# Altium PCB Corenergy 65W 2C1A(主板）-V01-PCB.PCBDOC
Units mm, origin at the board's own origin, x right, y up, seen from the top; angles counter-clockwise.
Board outline 87.3 x 91.75 mm, 2 copper layers (Top Layer, Bottom Layer), stack 0.325 mm thick; 53 components, 103 nets, 136 pads, 181 vias.
Unrouted connection lines stored in the file: 2.
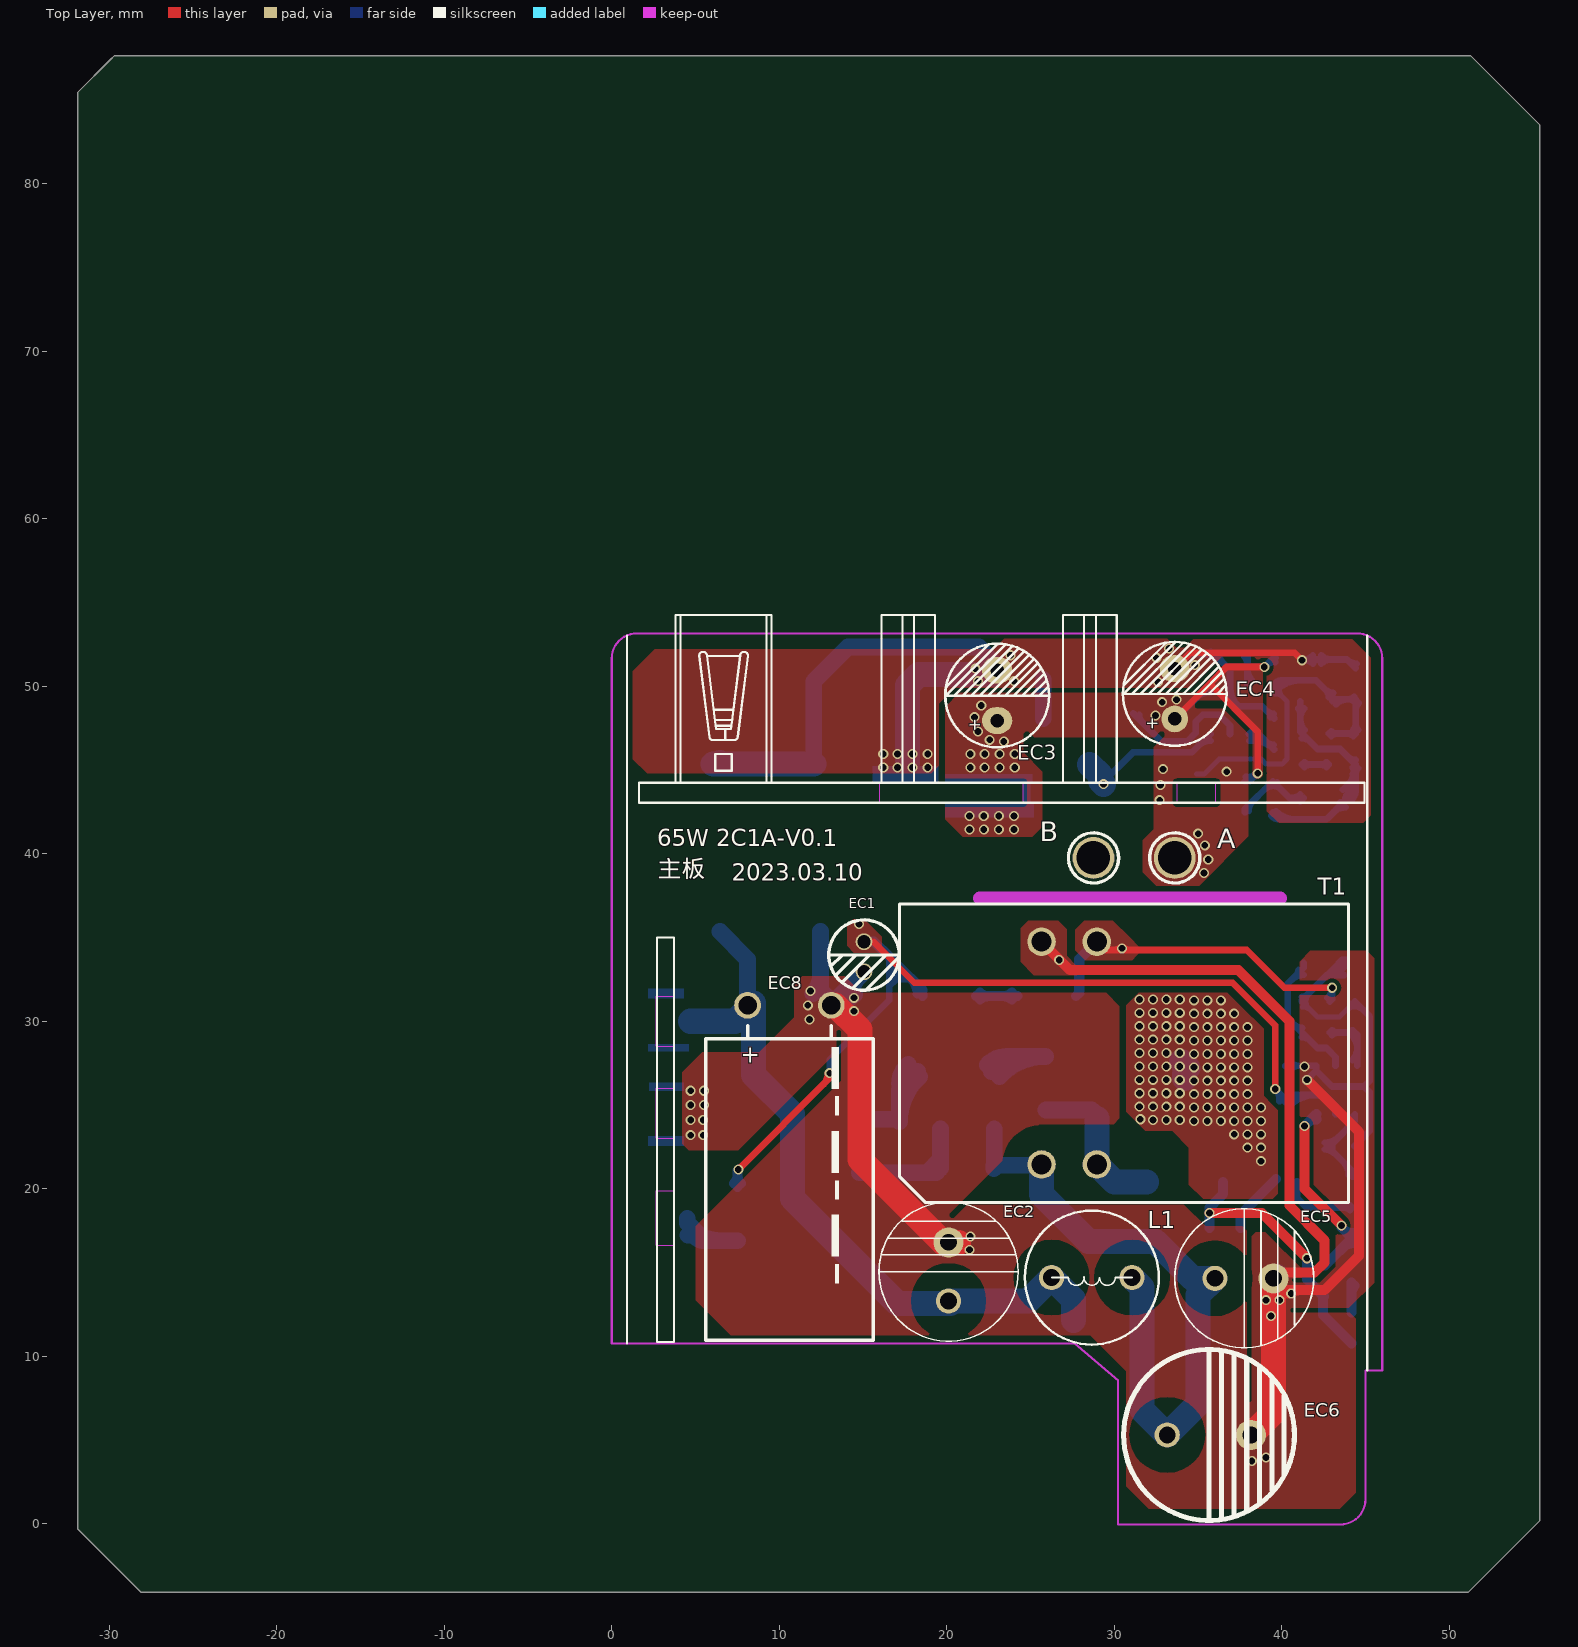
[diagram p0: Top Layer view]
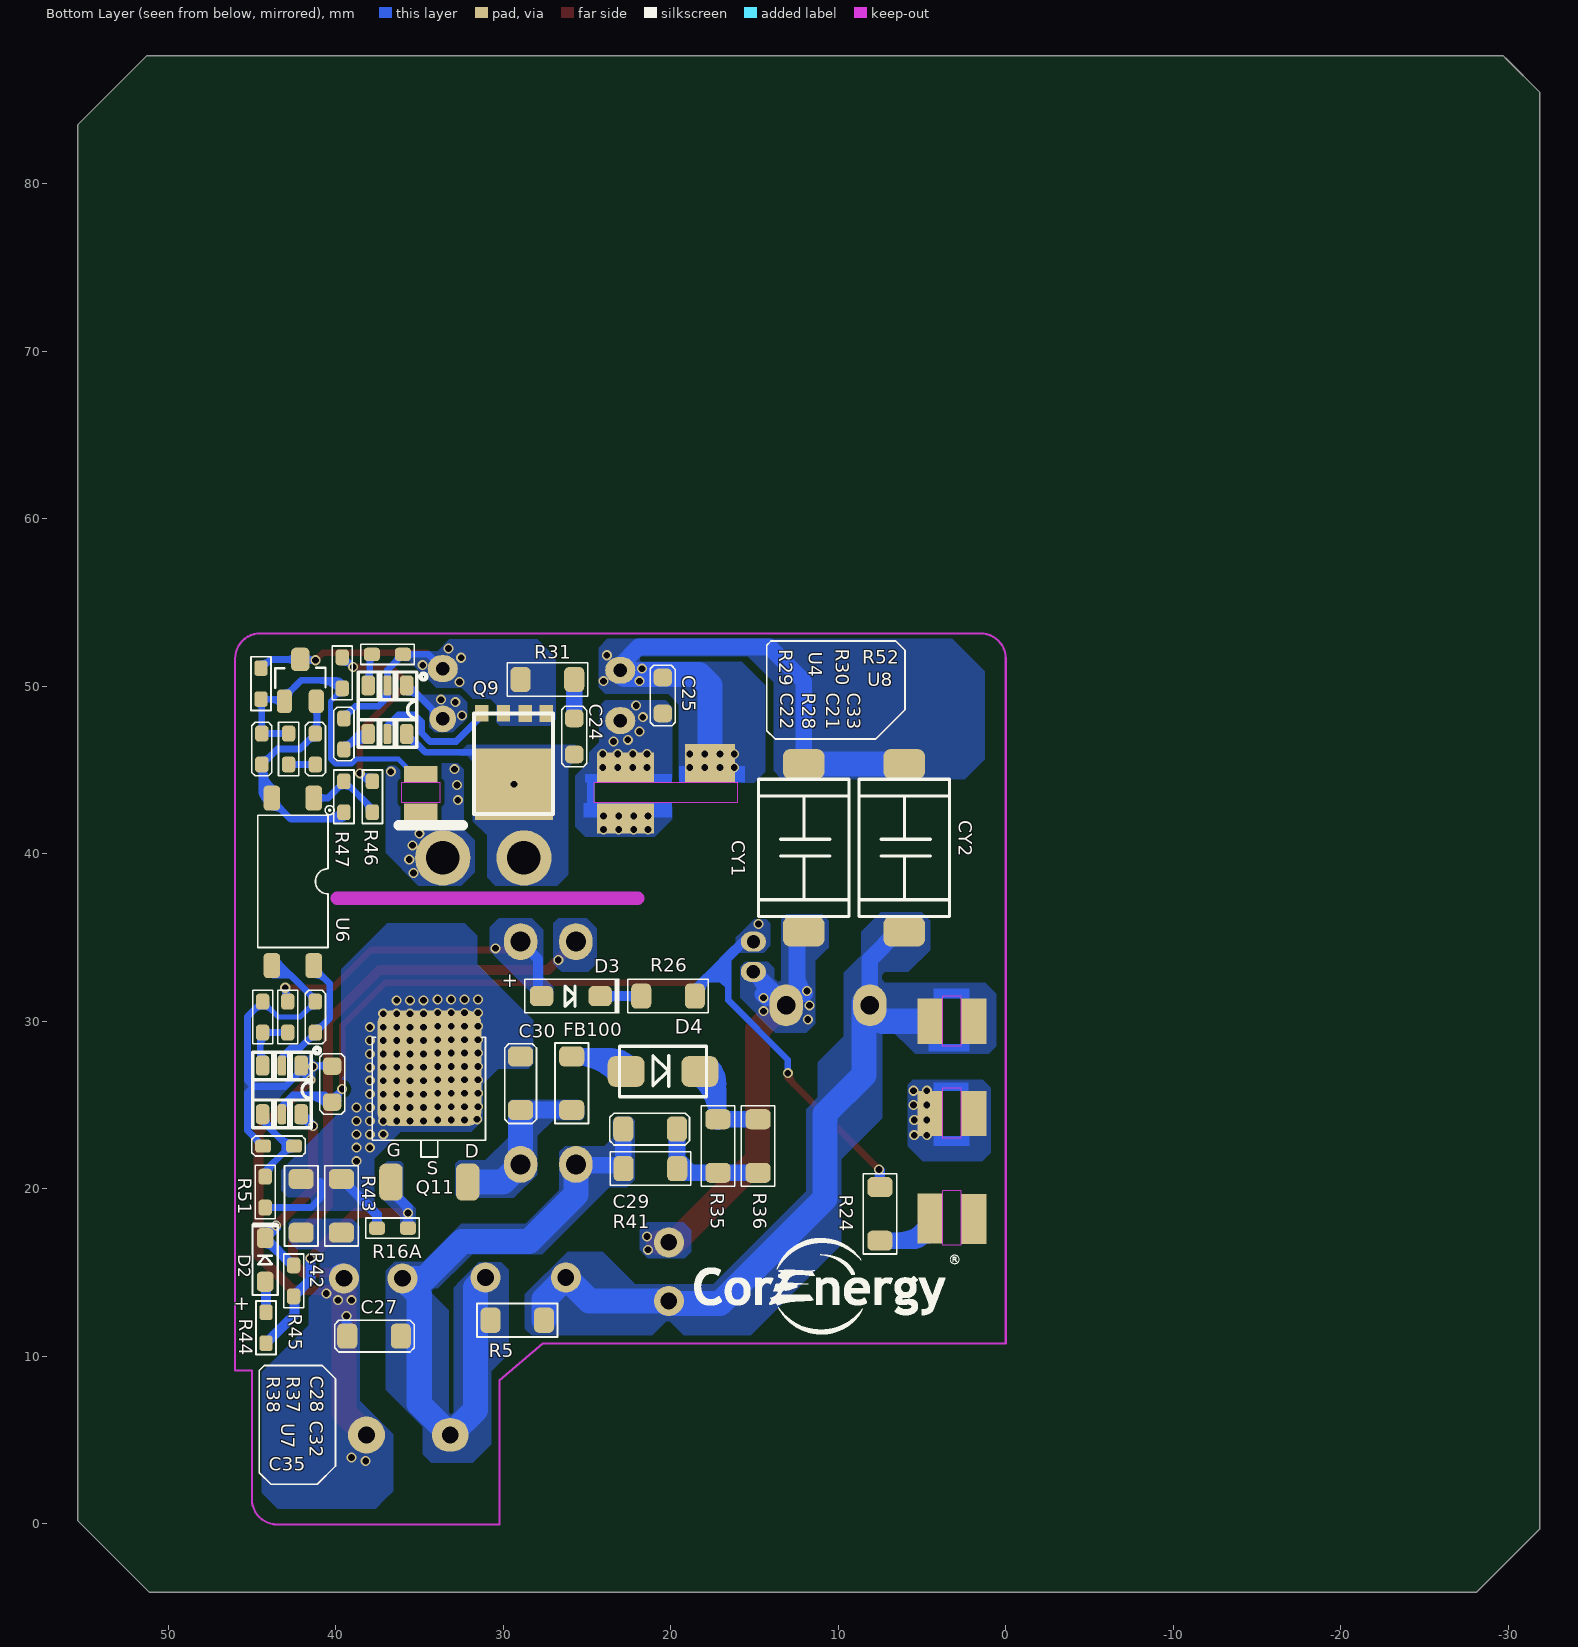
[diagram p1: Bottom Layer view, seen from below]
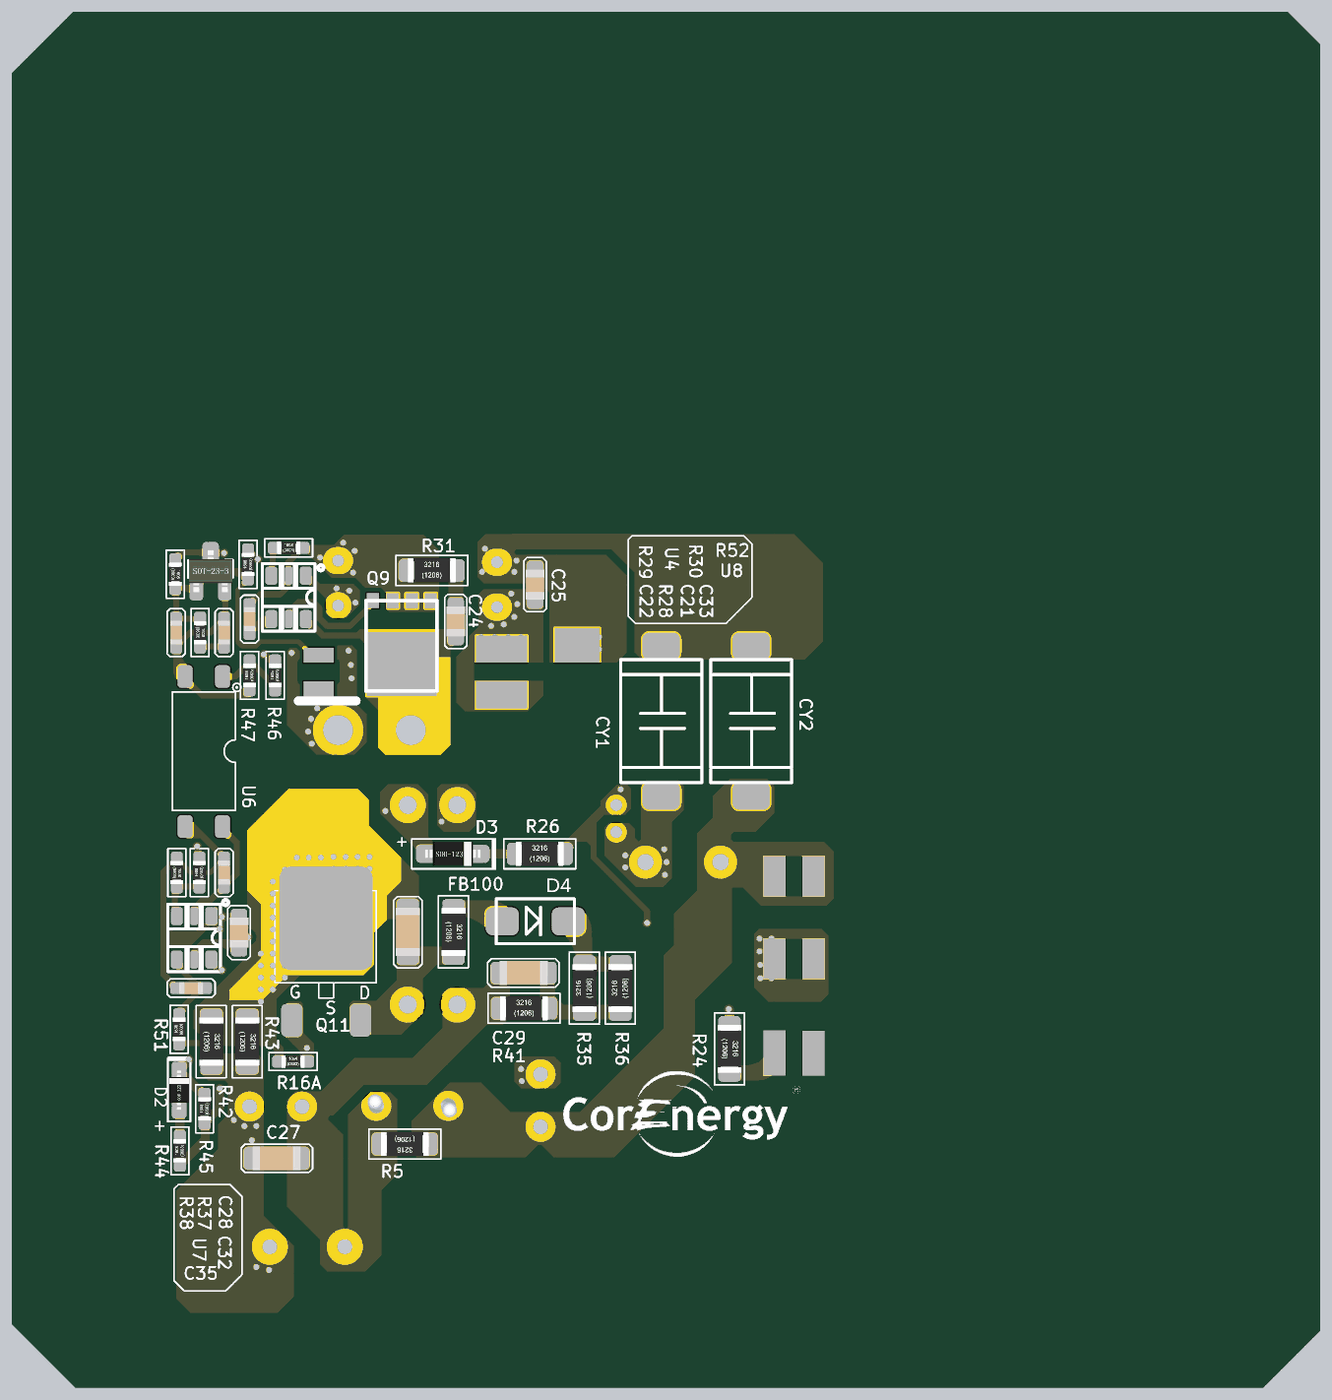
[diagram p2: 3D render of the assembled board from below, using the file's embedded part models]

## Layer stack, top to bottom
Top Layer: signal copper 0.0356
Dielectric: core 0.254, FR-4, Dk 4.2
Bottom Layer: signal copper 0.0356

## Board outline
-29.7,87.65 51.25,87.65 55.4,83.5 55.4,0.2 51.1,-4.1 -28.1,-4.1 -31.9,-0.3 -31.9,85.45 -29.95,87.4

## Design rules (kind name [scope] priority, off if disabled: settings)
Clearance Clearance_1 [InNet('GND') vs InNetClass('New Class')] p1: gap=1.5
Clearance [All] p2: gap=0.25
ComponentClearance [All] p1: gap=0 collisioncheckmode=3 verticalgap=0 showdistances=FALSE
FabricationTestpoint [(IsPad And (OnTopLayer Or OnBottomLayer))] p1: side=3 testpointundercomponent=TRUE minsize=1.016 maxsize=2.54 preferedsize=1.524 minholesize=0 maxholesize=1.016 preferedholesize=0.813 testpointgrid=0.025 allowsidetop=TRUE allowsidebottom=TRUE usegrid=TRUE gridtolerance=0
PolygonConnect [All] p1: connectstyle=Direct reliefconductorwidth=0.254 reliefentries=4 polygonreliefangle="90 Angle" airgapwidth=0.254
RoutingVias [All] p1: holewidth=0.3 width=0.5 viastyle="Through Hole" minholewidth=0.3 minwidth=0.5 maxholewidth=10 maxwidth=10
SilkToSolderMaskClearance SilkscreenOverComponentPads [IsPad] p1: minsilkscreentomaskgap=0.254 clearancetoexposedcopper=TRUE
SolderMaskExpansion [All] p1: expansion=0.102
Width [All] p1: maxlimit=10 minlimit=0.2 preferedwidth=0.4
25 further rules are at their usual default settings.

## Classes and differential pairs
net class "New Class": NetC27_1 NetC30_1 VH

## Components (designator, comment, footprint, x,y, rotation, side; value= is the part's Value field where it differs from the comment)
C21 "100nF" 0603C 41.2,46.25 r270 bottom (schematic designator C6)
C22 "100pF" 0603C 44.4,46.25 r90 bottom
C24 "1nF/250V" 0805C 25.75,47 r270 bottom (schematic designator C2)
C25 "100nF/50V" 0805C 20.46,49.447 r270 bottom
C27 "1nF/1KV" 1206C 37.7,11.2 r0 bottom (schematic designator C13)
C28 "1nF/50V" 0603C 41.2,30.25 r90 bottom (schematic designator C9)
C29 "1nF/1KV" 1206C 21.221,23.563 r180 bottom (schematic designator C1)
C30 "NC" 1206C 28.95,26.3 r90 bottom (schematic designator R20)
C32 "100NF/100V" 0805C 40.2,26.25 r90 bottom (schematic designator C8)
C33 "2.2uF/25V" 0603C 39.5,47.15 r90 bottom (schematic designator C4)
C35 "100PF" 0603C 43.4,22.55 r180 bottom (schematic designator C10)
CY1 "" SMD-YC 12.05,40.35 r270 bottom
CY2 "" SMD-YC 6.05,40.35 r270 bottom (schematic designator CY1)
D2 "IN4148" 323 44.2,15.75 r270 bottom
D3 "ES1JS" 123 25.95,31.5 r0 bottom (schematic designator D4)
D4 "S2MF" SMAF 20.45,27 r180 bottom (schematic designator D1)
EC1 "4.7uF/100V" RB4.0 15.05,34.95 r270 top (schematic designator EC8)
EC2 "25uF/400V" 8*12 20.1,15.05 r180 top
EC3 "470uF/25V" C-DIP-6.2/3.0#1 23,49.45 r0 top locked (schematic designator EC7)
EC4 "470uF/25V" C-DIP-6.2/3.0#2 33.6,49.55 r0 top locked (schematic designator EC6)
EC5 "25uF/400V" 8*12 37.75,14.65 r90 top
EC6 "33uF/400V" E10 35.65,5.3 r0 top (schematic designator CE5)
EC8 "33uF/400V" EC-CAP10HA16 8.1,30.95 r90 top locked
FB100 "0R" 1206R 25.9,26.3 r270 bottom
L1 "HWR8*12/40uH" T8*10 28.65,14.7 r180 top
Q9 "HGN070N12SL" Q-QFN5*6 32.2,41.85 r90 bottom (schematic designator Q1)
Q11 "CE65H270TOEI" Cascode-TO252-3L 34.4,23.8 r180 bottom
R5 "4.7K" 1206R 29.15,12.15 r0 bottom (schematic designator R1)
R16A "10K" 0603R 36.6,17.65 r180 bottom (schematic designator R20)
R24 "200k" 1206R 7.5,18.5 r270 bottom (schematic designator R12)
R26 "2R" 1206R 20.15,31.5 r180 bottom (schematic designator R9)
R28 "10k" 0603R 42.8,46.25 r270 bottom (schematic designator R16)
R29 "3.6K" 0603R 44.45,50.15 r270 bottom (schematic designator R14)
R30 "27.4K" 0603R 39.6,50.8 r90 bottom (schematic designator R19)
R31 "5.1R" 1206R 27.35,50.4 r180 bottom (schematic designator R1)
R35 "22R" 1206R 17.173,22.55 r90 bottom (schematic designator R5)
R36 "22R" 1206R 14.773,22.55 r90 bottom (schematic designator R5)
R37 "150k" 0603R 42.85,30.25 r90 bottom (schematic designator R16)
R38 "13k" 0603R 44.35,30.25 r270 bottom (schematic designator R24)
R41 "470K" 1206R 21.2,21.2 r180 bottom (schematic designator R2)
R42 "0.56R" 1206R 42.05,18.978 r270 bottom (schematic designator R23)
R43 "0.56R" 1206R 39.65,18.978 r270 bottom (schematic designator R22)
R44 "10R" 0603R 44.15,11.7 r90 bottom (schematic designator R15)
R45 "20R" 0603R 42.5,14.5 r90 bottom (schematic designator R17)
R46 "5.6K" 0603R 37.8,43.4 r90 bottom (schematic designator R11)
R47 "4.7K" 0603R 39.5,43.4 r90 bottom (schematic designator R13)
R51 "100R" 0603R 44.2,19.8 r90 bottom (schematic designator R21)
R52 "20K" 0603R 36.9,51.9 r180 bottom (schematic designator R8)
T1 "Comment" ATQ2516 30.6,28.1 r0 top locked
U4 "TL431" SOT-23 42.1,50.35 r180 bottom
U6 "EL1019" W_SO-4(P10)__EL1019 42.55,38.3 r270 bottom (schematic designator U3)
U7 "HY1602E" SOT-23-6 43.2,25.9 r270 bottom (schematic designator U2)
U8 "HY913" SOT-23-6 36.9,48.6 r270 bottom

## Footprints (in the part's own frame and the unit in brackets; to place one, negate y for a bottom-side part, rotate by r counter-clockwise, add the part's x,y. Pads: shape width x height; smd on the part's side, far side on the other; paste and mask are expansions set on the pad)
8*12 [mm]
  round 1.5 / inner round 1.8 / far side round 1.8 hole 1: 1(0,1.75)
  round 1.8 hole 1: 2(0,-1.75)
  silkscreen extent -4.15,-4.15 4.15,4.15
123 [mm]
  rrect50% 1.4x1.2 smd mask+0.03: 1(1.75,0) 2(-1.75,0)
  silkscreen extent -2.9,-1.05 2.75,1.05, body extent -1.85,-0.8 1.85,0.8, height 1.2
323 [mm]
  rrect50% 1.2x1 smd mask+0.03: 1(1.3,0) 2(-1.3,0)
  silkscreen extent -2.25,-0.75 2.1,0.75, body extent -1.3,-0.65 1.3,0.65, height 1
0603C [mm]
  rrect50% 0.95x0.8 smd mask+0.03: 1(-0.925,0) 2(0.925,0)
  silkscreen extent -1.6,-0.6 1.6,0.6, body extent -0.8,-0.4 0.8,0.4, height 0.8
0603R [mm]
  rrect50% 0.95x0.8 smd mask+0.03: 1(-0.925,0) 2(0.925,0)
  silkscreen extent -1.6,-0.6 1.6,0.6, body extent -0.77,-0.42 0.78,0.43, height 0.45
0805C [mm]
  rrect50% 1.05x1.1 smd mask+0.03: 1(-1.075,0) 2(1.075,0)
  silkscreen extent -1.8,-0.75 1.8,0.75, body extent -1,-0.62 1,0.63, height 0.6
1206C [mm]
  rrect50% 1.2x1.5 smd mask+0.03: 1(-1.6,0) 2(1.6,0)
  silkscreen extent -2.4,-0.95 2.35,0.95, body extent -1.6,-0.8 1.6,0.8, height 0.79
1206R [mm]
  rrect50% 1.2x1.5 smd mask+0.03: 1(-1.6,0) 2(1.6,0)
  silkscreen extent -2.4,-1 2.4,1, body extent -1.6,-0.8 1.6,0.8, height 0.55
ATQ2516 [mm]
  round 1.7 / inner round 1.7 / far side oval 2x2.2 hole 1.2: 1(-4.95,-6.65) 2(-1.65,-6.65) 7(-1.65,6.65) 8(-4.95,6.65)
  silkscreen extent -13.42,-8.93 13.39,8.9, body extent -13.43,-8.95 13.45,8.97, height 20.5
C-DIP-6.2/3.0#1 [mm]
  oval 1.8x1.6 hole 0.8: 1(0,-1.5) 2(0,1.5)
  silkscreen extent -3.1,-3.1 3.1,3.1
C-DIP-6.2/3.0#2 [mm]
  round 1.6 hole 0.8: 1(0,-1.5)
  oval 1.8x1.6 hole 0.8: 2(0,1.5)
  silkscreen extent -3.1,-3.1 3.1,3.1
Cascode-TO252-3L [mm]
  rrect50% 1.4x2.2 smd mask+0.03: 1(-2.29,-3.4) 3(2.29,-3.4)
  rrect25% 6.2x6.9 smd mask+0.03: 2(0,3.4)
  silkscreen extent -3.4,-1.9 3.35,5.25, body extent -3.3,-3.8 3.3,6.25, height 1.1
E10 [mm]
  round 1.5 / inner round 1.45 / far side oval 2.2x2 hole 1: 1(-2.5,0)
  round 1.8 / inner round 1.45 / far side round 2.2 hole 1: 2(2.5,0)
  silkscreen extent -5.1,-5.1 5.1,5.1
EC-CAP10HA16 [mm]
  round 1.6 / inner oval 2.5x2 / far side oval 2.5x2 hole 1.1: 1(0,0) 2(0,-5)
  silkscreen extent -20,-7.5 -1.2,2.5
Q-QFN5*6 [mm]
  rect 4.25x4.65 smd: D(2.3,-2.85)
  rect 1x0.8 smd: G(6.54,-0.92) S(6.52,-4.78) S(6.52,-3.52) S(6.53,-2.23)
  silkscreen extent 0.52,-5.19 6.52,-0.46
RB4.0 [mm]
  round 1 / inner oval 1.2x1.5 / far side oval 1.2x1.5 hole 0.8: 1(0.2,0) 2(2,0.001)
  silkscreen extent -1.1,-2.1 3.1,2.1
SMAF [mm]
  rrect50% 2.2x1.85 smd: 1(-2.2,0) 2(2.2,0)
  silkscreen extent -2.6,-1.5 2.6,1.5
SMD-YC [mm]
  rrect50% 1.8x2.5 smd: 1(5,0) 2(-5,0)
  silkscreen extent -4.1,-2.7 4.1,2.7
SOT-23 [mm]
  rrect50% 0.9x1.4 smd mask+0.03: 1(-0.95,-1.25) 3(0.95,-1.25)
  rrect50% 1.1x1.4 smd mask+0.03: 2(0,1.25)
  silkscreen extent -1.5,-0.45 1.5,0.75, body extent -1.45,-1.4 1.45,1.4, height 1.2
SOT-23-6 [mm]
  rrect50% 1.2x0.8 smd mask+0.03: 1(-1.45,1.15) 3(-1.45,-1.15) 4(1.45,-1.15) 6(1.45,1.15)
  rrect50% 1.2x0.5 smd mask+0.03: 2(-1.45,0) 5(1.45,0)
  silkscreen extent -2.53,-1.75 2.25,2.28
T8*10 [mm] "磁环电感"
  round 1.5 / inner round 1.5 / far side round 1.8 hole 1: 1(-2.4,0) 2(2.4,0)
  silkscreen extent -4,-4 4,4, body extent -3.5,-3.5 3.5,3.5, height 10.92
W_SO-4(P10)__EL1019 [mm]
  rrect50% 1.5x1 smd: 1(-5.025,1.25) 2(-5.025,-1.25) 3(4.975,-1.251) 4(4.975,1.25)
  silkscreen extent -4.57,-2.1 3.9,2.47

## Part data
C21 C22: library part CAP-1, "1206-big"
C24 C25 C30 C32: library part C0805, "cap"
C27 C29: library part CAP, "1NF/630V，COG/NPO,±5%,1206,C1206N102J631T"
C28: library part C0402, "cap"
C33 C35: library part C0603, "cap"
CY1 CY2: library part CY, "CY"
D2 D3 D4: library part DIODE, "Diode"
EC1 EC8: library part CE10
EC2 EC5 EC6: library part CE10, "27uF/400V，10*15mm"
EC3 EC4: library part CT6, "CAP-E"
FB100 R5 R16A R24 R26 R31 R35 R36 R38 R41 R42 R43 R45 R51 R52: library part RES, "resistance"
L1: library part IND-C, "ferrite inductor"
Q9: library part DFN8*8, "A1SH MOS管 AO3401"
Q11: library part DFN8*8
R28 R29 R30 R46 R47: library part RSE2
R37: library part RES2
R44: library part RES, "2R,±1%,0402"
U6: library part PC817, "EL1018（TA)(AES)-VG,SOP-4_P2.54_300mil,EVERLIGHT(台湾亿光)"
U7: library part MK2697G
U8: library part SC3503

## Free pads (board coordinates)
  rect 1.5x3 smd far side mask+0.03: 0(1.9,18.2) 0(4.5,18.222)
  rect 1.5x2.7 smd far side mask+0.03: 0(1.9,24.5) 0(1.9,30) 0(4.5,24.5) 0(4.5,30)
  rect 3x2.3 smd far side: 0(17.65,45.4)
  rect 3.4x1.8 smd far side: 0(22.7,42.1) 0(22.7,45.15)
  round 2.5 / inner round 2.5 / far side round 3.3 hole 2 mask+0.03: 0(28.75,39.75) 0(33.6,39.75)
  rect 2x1 smd far side: 0(34.9,42.5) 0(34.9,44.75)

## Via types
v1: diameter 0.6, hole 0.4, Top Layer to Bottom Layer, tented both sides, 181 vias

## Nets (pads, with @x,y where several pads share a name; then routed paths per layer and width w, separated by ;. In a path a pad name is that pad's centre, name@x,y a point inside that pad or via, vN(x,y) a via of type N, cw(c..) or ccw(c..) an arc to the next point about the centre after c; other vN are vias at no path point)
$$$3: 
$$$11: 
$$$13: 
$$$16: 
$$$18: 
$$$20: 
$$$24: 
$$$27: 
$$$28: 
$$$29: 
$$$31: 
$$$32: 
$$$37: 
$$$39: 
$$$40: 
$$$43: 
$$$51: 
BST2: 
CC1: 
CC2: 
COMP2: 
DMA2: 
DMA2-R: 
DMC: 
DPA2-R: 
DPC: 
EN: 
FB-G: 
FB_IC: 
GND: C27.2 C28.2 C32.2 C35.1 CY1.1 EC1.2 EC2.2 EC5.2 EC6.2 EC8.2 pad.0@1.9,24.5 pad.0@4.5,24.5 R38.1 R42.2 R43.2 T1.8 U6.3 U7.1 | length 127.6
  Top Layer w0.6: T1.8 27.35,33.05 37.4,33.05 40.45,30 40.45,19 42.55,16.9 42.55,15.6 41.95,15 40.05,15 39.5,14.45 40,13.95 42.55,13.95 44.6,16 44.6,23.4 v1(41.5,26.5) ; EC5.2@39.953,13.997 ccw(c40.55,14.595) v1(40.55,13.75) ; EC5.2@40,13.95 ccw(c40.489,14.439) v1(40.55,13.75) ; 40.067,13.95 cw(c40.067,13.267) v1(40.55,13.75) ; 41.033,13.95 ccw(c41.033,13.267) v1(40.55,13.75)
  Top Layer w1.5: EC8.2@13.325,30.975 14.8,29.5 14.8,21.75 EC2.2@19.85,16.7 ; EC2.2@19.95,16.8 EC2.2@20.7,16.8 ; EC6.2 39.5,6.65 EC5.2@39.5,14.45
  Bottom Layer w0.3: C28.2@41.2,30.85 cw(c41.2,30.065) 41.755,30.62 ; C28.2 42.125,30.25 43.425,30.25 R38.1 ; C28.2@41.45,31.1 ccw(c41.872,31.1) C28.2@41.574,30.801 ; 43.795,30.62 cw(c44.35,30.065) R38.1@44.35,30.85 ; R38.1@43.976,30.801 ccw(c43.678,31.1) R38.1@44.1,31.1
  Bottom Layer w0.4: C32.2 40.225,27.35 U7.1 U7.1@42.05,27.05 ; C32.2@40.455,27.095 cw(c41.07,26.48) v1@41.07,27.35 ; C32.2@40.455,27.555 ccw(c40.949,28.049) 40.949,27.35 ; 40.988,27.35 cw(c40.988,26.938) v1@41.279,27.229 ; C28.2 41.2,31.261 42.689,32.75 ; C28.2@41.2,31.45 ccw(c41.2,31.907) C28.2@41.523,31.584 ; C28.2@41.4,31.25 cw(c41.909,31.25) 41.549,31.61 ; v1@41.421,27.229 cw(c41.712,26.938) U7.1@41.712,27.35 ; v1(41.5,26.5) U7.1@42.05,27.05 ; U6.3 43.581,33.105 43.045,33.105 ; U6.3@43.801,33.675 43.614,33.675 43.045,33.105 ; C35.1 45.25,23.475 45.25,25.74 44.89,26.1 ; R38.1@44.35,30.9 cw(c44.35,30.236) 44.819,30.706 ; R38.1 45.25,30.275 45.25,26.46 44.89,26.1 ; C35.1@44.6,22.55 cw(c45.264,22.55) 44.794,23.019 ; U7.1@42.05,27.05 43,26.1 44.89,26.1 ; 42.689,32.75 42.795,32.855 ; 42.689,32.75 43.7,32.75 43.595,32.855 42.795,32.855 ; 42.795,32.855 43.045,33.105
  Bottom Layer w0.6: C27.2 39.35,11.25 v1(39.35,12.4)
  Bottom Layer w1: v1@11.991,31.659 ccw(c10.884,32.766) 12.45,32.766 ; CY1.1@12.45,35.35 12.45,31.85 13.1,31.2 EC8.2@13.301,31.2 ; v1@14.25,31.4 cw(c16.058,31.4) EC1.2@14.78,32.679 ; v1@14.476,31.598 ccw(c14.292,30.209) EC8.2@13.301,31.2 ; EC1.2 EC8.2@13.301,31.2
  Bottom Layer w1.5: EC5.2 EC5.2@39.65,14.8
  other v1: 38.2,3.75 39.05,3.95 39.05,13.35 39.85,13.35 21.35,16.35 21.4,17.15 4.7,23.2 5.45,23.2 4.7,24.1 5.45,24.1 4.7,25 5.5,25 4.7,25.85 5.5,25.85 41.35,27.3 11.8,30.1 14.45,30.6 11.7,30.95 14.45,31.4 11.85,31.8 26.7,33.65
HGATE2: 
L: 
LGATE2: 
N: 
NetC5_1: 
NetC10_1: 
NetC21_1: C21.1 C22.1 R47.1 U4.3 U6.2 | length 24.7
  Bottom Layer w0.4: R47.1@39.359,42.259 ccw(c39.862,42.762) 39.862,42.05 ; R47.1@39.45,42.475 39.875,42.05 42.65,42.05 43.8,43.2 U6.2 44.4,43.925 ; R47.1@39.641,42.541 ccw(c40.828,43.728) 40.828,42.05 ; U4.3@40.973,48.673 cw(c40.667,48.367) 41.1,48.367 ; 41.1,47.974 ccw(c41.924,47.974) C21.1@41.341,47.391 ; 41.1,48.126 cw(c41.874,48.126) U4.3@41.327,48.673 ; U4.3@41.1,49.1 41.1,47.275 C21.1 42.125,46.25 43.475,46.25 C22.1 ; C21.1@41.2,46.9 cw(c41.2,46.236) 41.669,46.706 ; 43.074,42.474 cw(c43.8,41.749) U6.2@43.8,42.775 ; U6.2@43.376,42.776 ccw(c43.078,43.075) U6.2@43.5,43.075 ; U6.2@43.626,43.819 ccw(c42.549,45.325) C22.1 ; U6.2@43.858,43.494 ccw(c43.105,44.547) 44.4,44.547 ; U6.2@43.93,43.845 ccw(c44.109,44.216) 44.4,43.925 ; 43.931,45.794 ccw(c44.4,46.264) C22.1@44.4,45.6 ; U6.2@44.091,43.168 ccw(c43.661,43.769) 44.4,43.769 ; C22.1@44.227,45.15 cw(c43.866,44.942) 44.268,44.834 ; 44.244,44.743 cw(c44.775,44.601) C22.1@44.5,45.077 ; C22.1@44.259,45.109 cw(c43.917,44.767) 44.4,44.767 cw(c44.883,44.767) C22.1@44.541,45.109 ; 44.4,43.925 C22.1
NetC21_2: C21.2 R28.2 | length 3.1
  Bottom Layer w0.4: C21.2 R28.2 ; C21.2@41.341,45.184 cw(c41.683,44.842) 41.683,45.325 cw(c41.683,45.808) C21.2@41.341,45.466 ; R28.2@42.659,45.184 ccw(c42.317,44.842) 42.317,45.325 ccw(c42.317,45.808) R28.2@42.659,45.466
NetC22_2: C22.2 pad.0@34.9,42.5 pad.0@34.9,44.75 R28.1 R29.2 R30.1 U4.1 | length 28.6
  Bottom Layer w0.3: pad.0@34.9,44.75 35.35,44.75 36.25,45.65 38.751,45.65 39.051,45.35 39.999,45.35 40.3,45.651 40.3,49.1 R30.1@39.75,49.65 ; R30.1@39.6,49.55 cw(c39.6,48.946) 40.027,49.373 cw(c40.454,49.8) R30.1@39.85,49.8
  Bottom Layer w0.4: R30.1@39.459,50.091 cw(c40.083,49.467) 40.083,50.35 ; R30.1 40.075,50.35 42.05,50.35 43,49.4 43,49.1 43.125,49.225 44.4,49.225 C22.2 R28.1 ; R30.1@39.6,50.15 ccw(c39.6,50.814) 40.069,50.344 ; R30.1@39.741,49.809 cw(c41.049,48.501) 41.049,50.35 ; U4.1@42.8,49.35 ccw(c42.196,49.35) 42.623,49.777 ccw(c43.05,50.204) U4.1@43.05,49.6 ; R28.1@42.941,47.034 cw(c43.283,46.692) 43.283,47.175 cw(c43.283,47.658) R28.1@42.941,47.316 ; U4.1@43.227,48.923 cw(c43.955,48.195) 43.955,49.225 ; C22.2@44.259,47.034 ccw(c43.917,46.692) 43.917,47.175 ccw(c43.917,47.658) C22.2@44.259,47.316 ; C22.2@44.259,47.391 ccw(c43.917,47.733) 44.4,47.733 ccw(c44.883,47.733) C22.2@44.541,47.391 ; R29.2@44.309,49.084 ccw(c43.967,48.742) 43.967,49.225 ccw(c43.967,49.708) R29.2@44.309,49.366 ; 44.4,48.546 cw(c45.054,48.546) R29.2@44.591,49.009
NetC24_1: C24.1 R31.2 | length 2.3
  Bottom Layer w1: C24.1 R31.2
NetC26_1: R37.1 R38.2 U7.3 | length 6.6
  Bottom Layer w0.4: R37.1 R38.2 44.5,29.175 U7.3@44.5,27.35 ; R37.1@42.991,29.184 cw(c43.333,28.842) 43.333,29.325 cw(c43.333,29.808) R37.1@42.991,29.466 ; U7.3@44.209,27.691 ccw(c43.505,28.395) 44.5,28.395 ; R38.2@44.209,29.109 cw(c43.505,28.405) 44.5,28.405 ; R38.2@44.209,29.184 ccw(c43.867,28.842) 43.867,29.325 ccw(c43.867,29.808) R38.2@44.209,29.466
NetC27_1: C27.1 C29.1 EC5.1 EC6.1 L1.1 R5.2 R41.1 T1.1 | length 40.3
  Bottom Layer w1: R41.1 22.821,21.221 C29.1 ; R41.1@22.8,21.4 25.6,21.4 T1.1
  Bottom Layer w1.5: T1.1 25.65,19.65 28.45,16.85 32.45,16.85 34.65,14.65 EC5.1 35,13.65 35,7.15 EC6.1 31.65,6.8 31.65,14.1 L1.1
NetC28_1: C28.1 U6.4 U7.2 | length 10.2
  Bottom Layer w0.4: 40.575,32.475 cw(c41.3,31.749) U6.4@41.3,32.775 ; 40.731,29.794 ccw(c41.2,30.264) C28.1@41.2,29.6 ; U6.4@40.876,32.776 ccw(c40.577,33.075) U6.4@41,33.075 ; C28.1@41.2,29.05 cw(c41.2,28.386) 41.669,28.856 ; U6.4@41.3,33.5 41.3,33.2 40.35,32.25 40.35,30.175 C28.1 42.125,28.4 42.65,28.4 43.2,27.85 U7.2
NetC29_2: C29.2 R35.1 R36.1 R41.2 | length 9.2
  Bottom Layer w1: R36.1 R35.1 18.8,20.95 ; 19.621,22.55 R41.2@19.621,21.771 ; C29.2 R41.2@19.621,21.771 ; 18.8,20.95 R41.2@19.621,21.771 ; 18.8,20.95 19.35,20.95 R41.2 19.621,21.221 R41.2@19.621,21.771
NetC30_1: C30.1 FB100.2 Q11.3 T1.2 | length 9.3
  Bottom Layer w1: FB100.2 28.65,24.7 C30.1@28.95,24.4
  Bottom Layer w1.5: C30.1@28.95,24.2 T1.2 30,20.4 Q11.3@31.91,20.4
NetC30_2: C30.2 Q11.2 R16A.1 R42.1 R43.1 R51.1 | length 9.9
  Bottom Layer w0.4: 40.9,20.45 40.9,19.45 41.475,18.875 R51.1 ; R51.1@44.059,18.734 ccw(c43.717,18.392) 43.717,18.875 ccw(c43.717,19.358) R51.1@44.059,19.016
  Bottom Layer w0.6: R16A.1 37.525,18.453 R43.1
  Bottom Layer w1.5: Q11.2@34,27.6 Q11.2 ; Q11.2@34.2,26.6 Q11.2@34.2,26.85
  other v1: 38.75,21.65 37.95,22.45 38.75,22.45 37.15,23.25 37.95,23.25 38.75,23.25 34.75,24.05 35.55,24.05 36.35,24.05 37.15,24.05 37.95,24.05 38.75,24.05 32.3,24.1 33.1,24.1 33.9,24.1 31.55,24.15 34.75,24.85 35.55,24.85 36.35,24.85 37.15,24.85 37.95,24.85 38.75,24.85 31.5,24.9 32.3,24.9 33.1,24.9 33.9,24.9 34.75,25.65 35.55,25.65 36.35,25.65 37.15,25.65 37.95,25.65 31.5,25.7 32.3,25.7 33.1,25.7 33.9,25.7 34.75,26.45 35.55,26.45 36.35,26.45 37.15,26.45 37.95,26.45 31.5,26.5 32.3,26.5 33.1,26.5 33.9,26.5 34.75,27.25 35.55,27.25 36.35,27.25 37.15,27.25 37.95,27.25 31.5,27.3 32.3,27.3 33.1,27.3 33.9,27.3 34.75,28.05 35.55,28.05 36.35,28.05 37.15,28.05 37.95,28.05 31.5,28.1 32.3,28.1 33.1,28.1 33.9,28.1 34.75,28.85 35.55,28.85 36.35,28.85 37.15,28.85 37.95,28.85 31.5,28.9 32.3,28.9 33.1,28.9 33.9,28.9 34.75,29.65 35.55,29.65 36.35,29.65 37.15,29.65 37.95,29.65 31.5,29.7 32.3,29.7 33.1,29.7 33.9,29.7 34.75,30.45 35.55,30.45 36.35,30.45 37.15,30.45 31.5,30.5 32.3,30.5 33.1,30.5 33.9,30.5 34.75,31.25 35.55,31.25 36.35,31.25 31.5,31.3 32.3,31.3 33.1,31.3 33.9,31.3
NetC32_1: C32.1 EC1.1 R24.1 R26.2 U7.5 | length 68.7
  Top Layer w0.4: v1(7.55,21.15) 13,26.6 v1(13,26.9) ; 12.617,26.217 ccw(c11.934,26.9) v1@12.9,26.9 ; EC1.1 15.6,34.75 18.05,32.3 37.05,32.3 39.6,29.75 v1(39.6,25.95)
  Bottom Layer w0.4: 7.5,20.788 cw(c7.912,20.788) v1@7.621,21.079 ; v1@7.5,21.1 v1(7.55,21.15) ; v1(13,26.9) 13,27.7 16.55,31.25 16.55,32.1 ; 16.55,33.85 16.55,33.1 ; 17.225,33.175 17.15,33.1 16.55,33.1 ; C32.1@39.852,25.215 ccw(c38.974,25.324) v1(39.6,25.95) 40.2,25.35 C32.1 40.625,25.6 42.55,25.6 43.2,24.95 U7.5 ; C32.1@40.172,25.228 cw(c41.07,24.33) 41.07,25.6 ; C32.1@40.455,24.945 cw(c42.036,23.364) 42.036,25.6 ; 43.009,25.141 cw(c42.667,24.8) U7.5@43.15,24.8 ; 16.55,32.1 16.55,32.75 ; 16.55,32.1 16.95,32.5 17.893,32.5 17.896,32.504 17.65,32.75 16.55,32.75 ; 16.55,32.75 16.55,33.1
  Bottom Layer w0.6: R24.1@7.288,20.312 ccw(c6.776,20.824) 7.5,20.824 ccw(c8.224,20.824) R24.1@7.712,20.312 ; R24.1 v1@7.5,21.1 ; EC1.1 15.65,34.75 16.55,33.85 17.225,33.175 17.65,32.75 17.896,32.504 ; R26.2@18.25,31.65 ccw(c17.043,31.65) 17.896,32.504 ; R26.2 18.55,31.85 17.896,32.504
  other v1: 14.75,35.8
NetC33_1: C33.1 U8.4 | length 5.7
  Bottom Layer w0.4: U8.4@38.032,47.149 cw(c38.134,46.039) 38.923,46.827 ; U8.4 38.6,47.15 C33.1@39.525,46.225 ; U8.4@38.068,46.751 cw(c38.237,44.937) C33.1@39.525,46.225 ; U8.4@38.191,47.009 cw(c38.533,46.667) 38.533,47.15 cw(c38.533,47.633) U8.4@38.191,47.291 ; 39.073,46.677 ccw(c39.5,47.104) C33.1@39.5,46.5 ; C33.1@39.55,46.225 C33.1@39.525,46.225
NetC35_2: C35.2 R51.2 U7.4 | length 9.2
  Bottom Layer w0.4: C35.2@42.55,22.35 cw(c42.55,21.505) 43.147,22.103 43.012,22.238 ; C35.2@42.55,22.75 ccw(c42.55,23.957) 43.404,23.104 ; 43.012,22.842 43.012,22.712 ; 43.682,21.568 cw(c42.914,20.8) R51.2@44,20.8 ; 43.867,23.567 ccw(c43.184,24.25) U7.4@44.15,24.25 ; R51.2@44.175,20.8 R51.2@44.2,20.775 ; R51.2 R51.2@44.2,20.775 ; R51.2@44.25,20.725 R51.2@44.2,20.775 ; U7.4 44.35,24.05 43.012,22.712 ; 43.012,22.238 44.2,21.05 R51.2@44.2,20.775 ; 43.012,22.238 42.7,22.55 42.85,22.55 43.012,22.712 ; 43.012,22.238 43.012,22.712
NetCX1_1: 
NetCX1_2: 
NetD2_1: D2.1 R44.2 | length 2.4
  Bottom Layer w0.4: D2.1@44.15,14.4 D2.1
  Bottom Layer w0.6: 44.15,13.746 cw(c44.804,13.746) D2.1@44.341,14.209 ; R44.2 D2.1@44.15,14.4
NetD2_2: D2.2 R45.2 U7.6 | length 13.5
  Top Layer w0.6: v1(41.35,23.75) 41.35,20 v1(43.55,17.8)
  Bottom Layer w0.6: v1(41.35,23.75) U7.6 ; v1@41.538,23.938 cw(c42.05,23.426) U7.6@42.05,24.15 ; R45.2@42.45,15.425 42.575,15.425 D2.2 43.55,17.7 v1(43.55,17.8) ; R45.2@42.5,15.6 ccw(c42.5,16.204) 42.927,15.777 ; 43.688,16.538 cw(c44.2,16.026) D2.2@44.2,16.75 ; v1@43.688,17.562 ccw(c44.2,18.074) D2.2@44.2,17.35
NetD3_1: D3.1 R37.2 T1.7 | length 21.6
  Top Layer w0.4: T1.7 29.45,34.25 37.9,34.25 40.15,32 v1(43,32) ; 29.967,34.25 ccw(c29.967,34.833) v1@30.379,34.421 ; v1@30.521,34.421 ccw(c30.933,34.833) 30.933,34.25
  Bottom Layer w0.4: R37.2@42.722,31.403 ccw(c42.222,32) v1(43,32) 43,31.325 R37.2 R37.2@42.85,31.35
  Bottom Layer w0.6: D3.1 27.9,31.7 27.9,33.7 T1.7
  other v1: 30.45,34.35
NetD3_2: D3.2 R26.1 | length 4.7
  Bottom Layer w0.6: R26.1 D3.2 ; R26.1@21.962,31.288 cw(c22.474,30.776) 22.474,31.5 cw(c22.474,32.224) R26.1@21.962,31.712 ; D3.2@23.888,31.288 ccw(c23.376,30.776) 23.376,31.5 ccw(c23.376,32.224) D3.2@23.888,31.712
NetD4_2: D4.2 R35.2 R36.2 | length 12.6
  Bottom Layer w1: R36.2 R35.2 17.173,25.923 D4.2 ; R35.2@17.173,24.011 cw(c20.778,24.011) D4.2@18.36,26.685 ; 17.173,25.595 cw(c18.155,25.595) D4.2@18.099,26.576 ; 17.173,26.263 cw(c18.741,26.263) D4.2@17.689,27.426 ; 17.226,25.976 ccw(c16.201,27) D4.2@17.65,27
NetDB1_1: 
NetDB1_2: 
NetDB1_4: 
NetEC8_1: 
NetF1_1: 
NetFB100_1: D4.1 FB100.1 | length 8
  Bottom Layer w1: D4.1@22.407,27.395 cw(c23.579,26.287) 23.579,27.9 ; D4.1 23.55,27.9 FB100.1 ccw(c25.9,24.095) D4.1@23.134,26.708
NetNTC1_1: 
NetQ8_2: 
NetQ8_3: 
NetQ9_D: C24.2 pad.0@28.75,39.75 Q9.D U8.6 | length 11.1
  Bottom Layer w0.4: Q9.D@29.2,44.15 31.1,46.05 34.619,46.05 35.719,47.15 U8.6 ; Q9.D@29.45,44.15 cw(c30.054,44.15) Q9.D@29.627,44.577 ; 35.015,46.445 cw(c35.75,45.71) U8.6@35.75,46.75
  Bottom Layer w1: pad.0@28.4,39.4 pad.0@28.75,39.75
  Bottom Layer w1.5: Q9.D@28.523,45.331 29.164,44.691 29.164,44.337 29.275,44.225 v1(29.35,44.15)
NetQ9_G: Q9.G U8.5 | length 8.8
  Bottom Layer w0.4: Q9.G@31.13,48.39 31.13,48.37 32.8,46.7 34.35,46.7 34.85,47.2 34.85,47.869 35.281,48.3 36.25,48.3 36.9,47.65 U8.5 ; Q9.G@31.48,48.29 ccw(c32.132,48.29) 31.671,47.829
NetQ11_1: Q11.1 R16A.2 R44.1 R45.1 | length 16.8
  Top Layer w0.6: v1(35.675,18.55) 38.8,18.55 v1(41.5,15.85)
  Bottom Layer w0.6: R16A.2 v1(35.675,18.55) ; 35.905,19.105 ccw(c36.46,18.55) v1(35.675,18.55) ; Q11.1@36.49,20.4 36.49,19.69 35.675,18.875 v1(35.675,18.55) ; v1(41.5,15.85) 41.5,14.575 R45.1 ; R45.1@42.45,13.575 42.45,12.475 R44.1
NetR1_1: pad.0@1.9,18.2 pad.0@4.5,18.222 R24.2 | length 8
  Bottom Layer w0.4: pad.0@4.5,18.222 pad.0@4.522,18.2
  Bottom Layer w1: pad.0@4.5,18.222 4.5,17.95 5.55,16.9 ; pad.0@4.54,17.225 cw(c4.728,16.078) 5.55,16.9 ; pad.0@4.677,17.649 ccw(c6.485,19.457) 6.485,16.9 ; pad.0@4.743,17.532 ccw(c5.55,17.732) 5.55,16.9 ; R24.2 5.55,16.9
NetR2_2: 
NetR46_1: R46.1 R47.2 U6.1 | length 7.9
  Bottom Layer w0.4: R46.1 37.8,42.675 39.45,44.325 40.45,43.325 U6.1 ; R46.1@38,42.55 cw(c38.785,42.55) 38.23,43.105 ; 38.945,43.82 cw(c39.5,43.265) 39.5,44.05 cw(c39.5,43.507) 39.884,43.891 ; R47.2@39.7,44.25 ccw(c40.122,44.25) R47.2@39.824,43.951 ; U6.1@41.088,43.113 ccw(c40.576,42.601) 40.576,43.325 ccw(c40.576,44.049) U6.1@41.088,43.537
NetR52_1: R52.1 U8.3 | length 3.1
  Bottom Layer w0.4: R52.1@37.759,51.759 cw(c37.296,51.296) 37.95,51.296 ; R52.1 37.95,51.775 U8.3@37.95,50.05 ; 37.95,50.974 ccw(c38.774,50.974) U8.3@38.191,50.391
NewNet1: 
NewNet01: 
NewNet2: 
NewNet03: 
NewNet04: 
NewNet4: 
NewNet5: 
NewNet05: 
NewNet6: 
NewNet7: 
NewNet8: 
NewNet9: 
NewNet10: 
NewNet11: 
NewNet12: 
NewNet13: 
NewNet14: 
NewNet15: 
NewNet16: 
NewNet22: 
PLUG: 
PLUGA: 
SCK: 
SDA: 
SGND: C25.1 C33.2 CY1.2 CY2.2 EC3.2 EC4.2 pad.0@17.65,45.4 Q9.S R29.1 R31.1 R52.2 U4.2 U8.2 | length 60.4
  Top Layer w0.4: EC4.2 34.55,52 40.75,52 v1(41.2,51.55)
  Bottom Layer w0.4: EC4.2 34.45,51.9 R52.2 36.9,50.975 U8.2 36.9,49.35 37.45,48.8 38.825,48.8 C33.2@39.55,48.075 ; R52.2@35.759,51.759 ccw(c35.417,51.417) 35.417,51.9 ccw(c35.417,52.383) R52.2@35.759,52.041 ; R52.2@36.25,51.9 ccw(c36.914,51.9) 36.444,51.431 ; U8.2@36.95,49.7 ccw(c37.916,49.7) 37.233,49.017 ; 39.116,48.509 ccw(c39.5,48.893) C33.2@39.5,48.35 ; C33.2@39.176,48.449 cw(c38.878,48.15) C33.2@39.3,48.15 ; v1@41.376,51.55 cw(c41.376,50.876) U4.2@41.853,51.353 ; U4.2@41.84,51.835 cw(c41.2,52.412) v1(41.2,51.55) 42.05,51.55 U4.2 43.875,51.6 R29.1@44.4,51.075 ; U4.2@42.347,51.353 cw(c42.945,50.755) 42.945,51.6 cw(c42.945,52.445) U4.2@42.347,51.847 ; 43.895,51.58 ccw(c44.45,52.135) R29.1@44.45,51.35
  Bottom Layer w1: CY1.2 12.05,50.3 14.092,52.342 21.908,52.342 23,51.25 EC3.2
  Bottom Layer w1.5: CY2.2 CY1.2 ; CY2.2@6.45,45.45 CY2.2@6.5,45.4 ; pad.0@17.65,45.4 17.65,50.05 18.3,50.7 22.75,50.7 EC3.2
  other v1: 16.2,45.15 17.05,45.15 17.95,45.15 18.85,45.15 16.2,45.95 17.05,45.95 17.95,45.95 18.85,45.95 32.6,50.25 21.85,50.3 24,50.3 21.7,51.05 34.8,51.255 32.5,51.7 23.8,51.85 33.255,52.25
SW2: 
V+: C25.2 EC3.1 EC4.1 pad.0@22.7,42.1 pad.0@22.7,45.15 pad.0@33.6,39.75 R30.2 R46.2 U8.1 | length 20.3
  Top Layer w0.4: EC4.1 35.7,50.15 ; v1(38.55,44.8) 38.55,47.3 35.7,50.15 ; v1(38.95,51.15) 36.7,51.15 35.7,50.15
  Bottom Layer w0.4: EC4.1 33.65,48.05 U8.1@35.65,50.05 ; 34.896,49.296 cw(c35.75,48.443) U8.1@35.75,49.65 ; R46.2 38.075,44.325 v1(38.55,44.8) cw(c38.011,45.339) R46.2@37.844,44.595 ; v1(38.95,51.15) 39.5,51.7 R30.2@39.625,51.7 ; v1@39.003,51.203 cw(c39.6,50.605) R30.2@39.6,51.45
  other v1: 35.35,38.85 35.6,39.65 35.4,40.5 35,41.2 21.35,41.45 22.2,41.45 23.1,41.45 24,41.45 21.35,42.25 22.2,42.25 23.1,42.25 24,42.25 32.7,43.2 32.75,44.1 36.7,44.9 32.9,45.05 21.4,45.15 22.25,45.15 23.15,45.15 24.05,45.15 21.4,45.95 22.25,45.95 23.15,45.95 24.05,45.95 23.4,46.7 22.55,46.8 21.85,47.3 21.65,48.15 32.45,48.25 22.05,48.85 32.85,49.05 33.7,49.2
VCC: 
VDD1: 
VDD2: 
VH: CY2.1 EC2.1 EC8.1 L1.2 pad.0@1.9,30 pad.0@4.5,30 R5.1 | length 43.7
  Bottom Layer w1: CY2.1@6.45,35.35 8.1,33.7 EC8.1@8.1,31.2
  Bottom Layer w1.5: pad.0@4.7,30 7.35,30 8.45,31.1 8.45,26.8 10.775,24.475 10.775,19.425 17.05,13.15 20.2,13.15 EC2.1@20.35,13.3 ; EC2.1 EC2.1@20.35,13.3 ; R5.1 27.55,13.4 L1.2 24.85,13.3 EC2.1@20.35,13.3

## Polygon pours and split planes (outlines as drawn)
V+ on Bottom Layer "Bottom-No Net" (solid, remove dead copper, pour order 112): 23.9,49.15 24.25,48.8 24.25,46.65 24.85,46.05 24.85,45.5 25.7,44.65 25.7,41.6 25.1,41 20.95,41 19.9,42.05 19.9,48.75 20.3,49.15
V+ on Bottom Layer "Bottom-No Net" (solid, pour order 122): 36.65,45.4 37,45.05 37,40.05 35.05,38.1 32.5,38.1 31.7,38.9 31.7,40.8 32.35,41.45 32.35,45.05 32.7,45.4
SGND on Bottom Layer "Bottom-No Net" (solid, pour order 114): 23.75,52.85 24.3,52.3 24.3,49.95 23.9,49.55 20.15,49.55 19.5,48.9 19.5,44.46 19.29,44.25 15,44.25 14.35,44.9 14.35,50.05 15.75,51.45 21.75,51.45 21.85,51.55 21.85,51.7 21.75,51.8 15.4,51.8 13.85,50.25 13.85,44.95 13.35,44.45 2.45,44.45 1.25,45.65 1.25,50.9 3.2,52.85
SGND on Bottom Layer "Bottom-No Net" (solid, pour order 113): 33.2,52.8 33.9,52.1 35.75,52.1 35.9,51.95 35.9,51.5 35.6,51.5 34,49.9 32.45,49.9 31.8,49.25 30.75,49.25 30.4,48.9 30.4,47.85 30.2,47.65 27.2,47.65 26.85,48 26.85,51.7 27.95,52.8
NetQ9_D on Bottom Layer "Bottom-No Net" (solid, pour order 120): 28.75,46.5 32.15,46.5 32.4,46.25 32.55,46.1 32.55,45.85 32.15,45.85 31.8,45.5 31.8,45.3 31.8,41.95 30.95,41.1 30.95,40.65 30.95,38.6 30.45,38.1 29.95,38.1 26.75,38.1 26.1,38.75 26.1,39.35 26.1,45.15 25.7,45.55 25.65,45.6 25.65,46.45 25.7,46.5 28.6,46.5
V+ on Bottom Layer "Bottom-No Net" (solid, pour order 111): 33.45,49.5 34.95,49.5 35.1,49.35 35.1,49.25 34.55,48.7 34.4,48.55 34.4,48.25 34.4,47.55 34.15,47.3 34.1,47.25 33.65,47.25 33,47.25 32.15,48.1 32.15,48.45 32.15,49.05 32.5,49.4 32.6,49.5 33.35,49.5
NetC30_2 on Bottom Layer "Bottom-No Net" (solid, pour order 104): 36.9,35.85 39.65,33.1 39.65,24.7 43.25,21.1 43.25,19.9 42.85,19.5 41.6,19.5 41.45,19.35 41.45,18.75 41.4,18.7 37.8,18.7 37.7,18.8 37.7,21.8 36.1,23.4 31.9,23.4 31.2,24.1 31.2,26.25 30.3,27.15 28.5,27.15 28.2,27.45 28.2,30.05 31.55,33.4 31.55,35.1 32.3,35.85
GND on Bottom Layer "Bottom-No Net" (solid, pour order 103): 45.45,26.85 45.45,24.85 45.05,24.85 45.05,25.2 44.85,25.4 43.4,25.4 43.05,25.75 42.6,26.2 42.15,26.65 42.05,26.65 42,26.65 41.9,26.55 41.85,26.5 41.85,26.45 41.85,26.35 41.7,26.2 41.35,26.2 41.2,26.35 41.2,26.95 40.95,27.2 40.95,27.55 41.15,27.55 41.25,27.65 41.55,27.95 42,27.95 42.15,27.95 42.45,27.65 42.45,26.9 43,26.35 43.45,26.35 44.65,26.35 44.75,26.45 45.15,26.85 45.45,26.85
NetQ11_1 on Bottom Layer "Bottom-No Net" (solid, pour order 102): 35.85,21.65 36.9,21.65 37.4,21.15 37.4,19.6 36.75,18.95 36.15,18.35 36.15,17.7 35.2,17.7 35.2,18.822 35.55,19.172 35.95,19.572 35.95,21.3 35.95,21.5 36.1,21.65
GND on Bottom Layer "Bottom-No Net" (solid, pour order 101): 40,18.2 42.55,18.2 42.8,17.95 42.8,16.9 42.6,16.7 42.3,16.4 41.4,16.4 41.15,16.4 40.95,16.2 40.95,15.9 40.95,14.15 41.4,13.7 41.6,13.5 41.6,11.85 43.8,9.65 44.4,9.05 44.4,7.55 44.4,1.85 43.45,0.9 37.6,0.9 37.05,1.45 36.55,1.95 36.55,4.6 36.55,5.35 37.65,6.45 38.55,7.35 38.55,11.9 38.55,17.75 39,18.2
NetC30_1 on Bottom Layer "Bottom-No Net" (solid, pour order 100): 29.5,25.3 29.7,25.1 29.7,23.05 31.05,21.7 32.65,21.7 32.85,21.5 32.85,19.65 32.65,19.45 29.35,19.45 27.95,20.85 27.95,23.15 27,24.1 25.3,24.1 25.15,24.25 25.15,24.95 25.5,25.3
GND on Bottom Layer "Bottom-No Net" (solid, pour order 99): 25.6,36.15 26.7,36.15 27,35.85 27,33.45 26.75,33.2 26.5,32.95 25.55,32.95 24.9,32.95 24.4,33.45 24.4,35.55 25,36.15
NetD3_1 on Bottom Layer "Bottom-No Net" (solid, pour order 98): 28.85,36.15 30.25,36.15 30.8,35.6 30.8,34.2 30.25,33.65 29.8,33.2 28.25,31.65 27,31.65 27,32.05 27.35,32.4 27.6,32.65 27.6,33.5 27.6,35.45 28.3,36.15
NetC32_1 on Bottom Layer "Bottom-No Net" (solid, pour order 97): 14.55,36.1 15,36.1 15.85,35.25 16.1,35 16.1,34.1 14.45,34.1 14.05,34.5 14.05,35.85 14.3,36.1
GND on Bottom Layer "Bottom-No Net" (solid, pour order 96): 11.7,36.4 13.1,36.4 13.4,36.1 13.4,32.45 13.5,32.35 13.6,32.35 13.7,32.45 13.8,32.55 13.8,32.8 13.8,33.15 14.1,33.45 14.2,33.55 14.7,33.55 15.55,33.55 15.75,33.35 15.85,33.25 15.85,32.95 15.85,31.4 13.95,29.5 13.75,29.3 12.95,29.3 11.9,29.3 11.45,29.75 11.35,29.85 11.35,32.05 11.35,33.6 10.75,34.2 10.55,34.4 10.55,35.2 10.55,36 10.95,36.4 11.25,36.4
GND on Bottom Layer "Bottom-No Net" (solid, pour order 95): 19.65,18 21.4,18 21.85,17.55 21.85,16.35 21.5,16 21.35,15.85 20.35,15.85 19.15,15.85 18.75,16.25 18.75,17.55 19.2,18
NetC27_1 on Bottom Layer "Bottom-No Net" (solid, pour order 94): 22.6,24.3 23.25,24.3 23.4,24.15 23.45,24.1 23.45,23.8 23.45,23.05 23.95,22.55 26.3,22.55 26.6,22.25 26.65,22.2 26.65,21.45 26.65,19.9 27.65,18.9 28.65,17.9 31.45,17.9 32.5,17.9 33.3,17.1 34.75,15.65 35.7,15.65 36.45,15.65 37,15.1 37,14.8 37,8 34.8,5.8 34.8,5.05 34.8,4.15 34.3,3.65 31.8,3.65 31.05,4.4 30.7,4.75 30.7,7.85 30.7,9.1 30.2,9.6 29.65,10.15 29.65,14.3 29.65,15.15 30.1,15.6 31.45,15.6 32.25,14.8 32.55,14.5 32.95,14.1 32.95,6.7 32.95,6.65 33.05,6.55 33.15,6.55 33.25,6.65 33.25,12.5 33.25,12.75 34.25,13.75 34.25,13.9 34.1,14.05 33.9,14.05 32.15,15.8 31.85,16.1 30.85,16.1 27.65,16.1 25.25,18.5 23.65,20.1 23.1,20.1 22.6,20.1 22.15,20.55 22.15,24.1 22.35,24.3
GND on Bottom Layer "Bottom-No Net" (solid, pour order 93): 5.55,26.5 5.85,26.2 5.85,22.55 4.95,21.65 1.4,21.65 0.89,22.16 0.89,26.04 1.35,26.5
VH on Bottom Layer "Bottom-No Net" (solid, pour order 92): 7.45,36.5 8.6,35.35 8.6,33.95 9.65,32.9 9.65,29.1 11.2,27.55 11.2,25.45 11.9,24.75 11.9,19.85 17.45,14.3 22.1,14.3 24.05,16.25 26.15,16.25 28.7,13.7 28.7,11.65 28.3,11.25 21.1,11.25 20.25,12.1 20.05,12.1 19.2,11.25 15.2,11.25 9.8,16.65 9.8,21.75 7.35,24.2 7.35,29.5 7.15,29.7 7.05,29.7 5.4,28.05 1,28.05 0.55,28.5 0.55,31.65 1.2,32.3 7.2,32.3 7.4,32.5 7.4,32.75 7.2,32.95 5.8,32.95 4.5,34.25 4.5,36 5,36.5
V+ on Top Layer "Bottom-No Net" (solid, remove dead copper, pour order 115): 35.35,49.6 34.8,49.05 34.8,48.75 34.9,48.65 36.5,48.65 38,47.15 38,41.05 35.05,38.1 32.5,38.1 31.7,38.9 31.7,40.8 32.35,41.45 32.35,46.35 33,47 33,47.2 32.9,47.3 32.75,47.3 32.4,46.95 25.2,46.95 24.85,47.3 24.7,47.3 24.55,47.15 24.55,46.05 25.7,44.9 25.7,41.6 25.1,41 20.95,41 19.9,42.05 19.9,48.75 20.75,49.6
V+ on Top Layer "Bottom-No Net" (solid, pour order 124): 37.25,51.35 38.9,51.35 39,51.25 38.75,51 38.85,50.9 38.85,44.85 38.85,44.65 38.7,44.5 38.4,44.5 38.25,44.65 38.25,47.3 37.2,48.35 36.4,49.15 34.7,49.15 34.7,49.45 35.4,50.15 36.6,51.35 37.1,51.35
SGND on Top Layer "Bottom-No Net" (solid, pour order 117): 44.2,52.8 45.3,51.7 45.3,42.3 44.85,41.85 39.8,41.85 39.1,42.55 39.1,51 38.35,51.75 36.4,51.75 34.55,49.9 20.45,49.9 19.5,48.95 19.5,45.25 19.05,44.8 2.1,44.8 1.25,45.65 1.25,50.9 2.55,52.2 22.8,52.2 23.45,52.85 33.15,52.85 33.7,52.3 34.2,52.3 34.7,52.8
GND on Top Layer "Bottom-No Net" (solid, pour order 110): 13.9,32.7 14.9,31.7 29.5,31.7 30.3,30.9 30.3,24.4 33.9,20.8 33.9,19.3 35.45,17.75 38.65,17.75 40.6,15.8 40.6,12.9 40.5,12.8 40.5,12.7 40.6,12.6 44.05,12.6 44.4,12.25 44.4,1.85 43.45,0.9 32.05,0.9 30.7,2.25 30.7,9.1 28.55,11.25 7.1,11.25 5,13.35 5,17.75 13.7,26.45 13.7,29.4 13.6,29.5 13.5,29.5 13.4,29.4 13.4,28.15 7.55,22.3 4.6,22.3 4.2,22.7 4.2,26.95 5.4,28.15 8.8,28.15 10.9,30.25 10.9,32.25 11.35,32.7
NetC30_2 on Top Layer "Bottom-No Net" (solid, pour order 109): 33.2,31.7 36.75,31.7 37.55,30.9 38.9,29.55 38.9,25.8 38.9,25.55 39.4,25.05 39.75,24.7 39.75,22.4 39.75,19.7 39.45,19.4 36.3,19.4 35.3,19.4 34.45,20.25 34.45,22.45 33.45,23.45 31.85,23.45 31.15,24.15 30.7,24.6 30.7,29.7 30.7,30.95 31.45,31.7
GND on Top Layer "Bottom-No Net" (solid, pour order 108): 45.05,34.2 45.5,33.75 45.5,14.4 44,12.9 38.7,12.9 38.5,13.1 38.5,15.75 38.95,16.2 40.2,16.2 41.15,15.25 41.15,14.7 40.7,14.7 40.6,14.6 40.6,14.5 40.7,14.4 42.25,14.4 43.2,15.35 43.2,18.95 41.05,21.1 41.05,33.55 41.7,34.2
NetC32_1 on Top Layer "Bottom-No Net" (solid, pour order 107): 14.45,36.1 15.05,36.1 16.1,35.05 16.1,34.15 16.05,34.1 14.55,34.1 14.45,34.1 14.05,34.5 14.05,35.75 14.4,36.1
GND on Top Layer "Bottom-No Net" (solid, pour order 106): 25.4,36 26.65,36 27.15,35.5 27.15,33.9 27.7,33.35 27.75,33.3 27.75,32.75 25.2,32.75 24.4,33.55 24.4,35.55 24.85,36 25.1,36
NetD3_1 on Top Layer "Bottom-No Net" (solid, pour order 105): 28.95,36 29.9,36 30.9,35 31.45,34.45 31.45,34.05 31.3,33.9 31.05,33.65 28.7,33.65 28.25,33.65 27.65,34.25 27.65,35.45 28.2,36 28.65,36

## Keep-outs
Keep-Out Layer:
  lines w0.01: 2.65,16.622 2.65,19.872 3.75,19.872 3.75,16.622 2.65,16.622 ; 2.65,23 2.65,26 3.75,26 3.75,23 2.65,23 ; 2.65,28.5 2.65,31.5 3.75,31.5 3.75,28.5 2.65,28.5 ; 16,43.041 24.55,43.041 24.55,44.25 16,44.25 16,43.041 ; 33.75,43.05 36.05,43.05 36.05,44.25 33.75,44.25 33.75,43.05
  lines w0.127: 9.25,53.156 15.83,53.156 ; 19.03,53.156 26.73,53.156 ; 29.93,53.156 44.49,53.156 cw(c44.49,51.656) 45.99,51.656 45.99,9.156 44.99,9.156 44.99,1.456 cw(c43.49,1.456) 43.49,-0.044 30.22,-0.044 30.22,8.556 27.62,10.756 -0.01,10.756 -0.01,51.656 cw(c1.49,51.656) 1.49,53.156 40.4,53.156
  lines w0.8: 21.95,37.35 39.9,37.35

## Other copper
Top Layer:
  pour cut-out: 37.642,17.75 37.9,17.492 37.9,7.35 38,7.25 38.1,7.25 38.2,7.35 38.2,17.15 38.45,17.4 39.15,17.4 39.15,17.5 38.9,17.75
  pour cut-out: 30.3,25.25 30.3,24.2 29.95,23.85 25.5,23.85 20.15,18.5 20.15,18.35 20.25,18.25 20.4,18.25 21.2,19.05 34.45,19.05 34.45,20.55 30.5,24.5 30.5,25.2 30.45,25.25
Bottom Layer:
  rectangle net V+: 24.55,42.75 25,44.51
  rectangle net V+: 19.9,42.15 25.2,43.041
  rectangle net V+: 19.9,44.25 25.1,44.75
  rectangle net SGND: 15.55,44.25 19.5,45.25
  rectangle net VH: 2.15,31.35 4.3,31.95
  rectangle net VH: 2.15,28.2 4.6,28.65
  rectangle net GND: 2.15,22.55 4.3,23.15
  rectangle net GND: 2.2,25.85 4.3,26.35
Multi-Layer:
  pour cut-out: 2.65,26 3.75,26 3.75,23 2.65,23
  pour cut-out: 2.65,31.5 3.75,31.5 3.75,28.5 2.65,28.5
  pour cut-out: 33.75,44.22 36.05,44.22 36.05,43.03 33.75,43.03

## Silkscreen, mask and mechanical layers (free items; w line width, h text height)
Top Overlay:
  circle w0.2: c28.75,39.75 r1.5
  circle w0.2: c33.6,39.75 r1.5
  lines w0.12: 2.7,10.85 3.7,10.85 3.7,35 2.7,35 2.7,10.85
  lines w0.127: 0.89,10.756 0.89,53.031 ; 4.105,44.256 4.105,54.256 ; 5.675,51.796 7.655,51.796 ; 6.07,48.599 7.26,48.599 ; 6.147,47.977 7.183,47.977 ; 6.165,45.256 6.175,45.256 ; 6.175,45.956 6.175,44.976 7.155,44.976 7.155,45.956 ; 6.189,47.643 7.141,47.643 ; 6.765,46.796 6.765,47.45 ; 7.155,45.256 7.165,45.256 ; 9.225,44.256 9.225,54.256 ; 16.09,44.241 16.09,54.256 19.29,54.256 19.29,44.241 ; 17.34,44.241 17.34,54.256 ; 18.04,44.241 18.04,54.256 ; 26.94,44.241 26.94,54.256 30.14,54.256 30.14,44.241 ; 28.19,44.241 28.19,54.256 ; 28.89,44.241 28.89,54.256 ; 45.09,9.156 45.09,53.031 ; 1.626,43.041 44.919,43.041 44.919,44.241 1.626,44.241 1.626,43.041 ; 3.805,44.256 9.525,44.256 9.525,54.256 3.805,54.256 3.805,44.256 ; 5.217,51.821 cw(c5.415,51.846) 5.415,52.046 5.469,52.046 cw(c5.469,51.846) 5.669,51.846 6.213,47.45 7.117,47.45 7.661,51.846 cw(c7.861,51.846) 7.861,52.046 7.915,52.046 cw(c7.915,51.846) 8.113,51.821 7.513,46.971 cw(c7.315,46.996) 7.315,46.796 6.015,46.796 cw(c6.015,46.996) 5.817,46.971 5.217,51.821 ; 6.165,44.956 7.165,44.956 7.165,45.956 6.165,45.956 6.165,44.956
  text "65W 2C1A-V0.1" at 2.7,40.45 h1
  text "B" at 25.55,40.35 h2
  text "A" at 36.15,39.95 h2
  text "2023.03.10" at 7.15,38.4 h1
  text "主板" at 2.75,38.25 h1.8
Bottom Overlay:
  drawing of 4151 lines, arcs and shapes, not listed
Bottom Solder:
  rectangle: 26.85,41.95 31.8,46.5
  region: 36.9,35.85 39.65,33.1 39.65,29.05 38.75,28.15 38.75,24.55 40.85,22.45 40.85,21.75 38.65,21.75 37,23.4 31.9,23.4 31.2,24.1 31.2,26.25 30.35,27.1 30.35,28.7 29.4,29.65 29.4,31.25 31.55,33.4 31.55,35.1 32.3,35.85
  region: 30.95,38.6 30.45,38.1 26.75,38.1 26.1,38.75 26.1,44.6 30.3,44.6 30.95,43.95
Mechanical 2:
  circle w0.2: c40.3,37.35 r3.3
  lines w1.5: 0.75,27.3 5.95,27.3 6.6,26.65 6.6,23.65 9.05,21.2 9.05,18.9 ; 1.7,20.8 5.4,20.8 6.45,21.85 ; 9.45,36.45 9.45,34.2 10.55,33.1 10.55,29.4 11.95,28 11.95,25.85 12.7,25.1 12.7,20.15 17.8,15.05 21.7,15.05 22.7,16.05 ; 26.7,23.25 27.25,22.7 27.25,20.45 29.05,18.65 32.8,18.65 35.05,16.4 36.75,16.4 37.75,15.4 37.75,7.65 35.6,5.5 35.6,3
  lines w1.6: -3.1,27.25 -1.15,27.25
  lines w6.5: 37.4,35.85 39.55,38 49.05,38
  lines w7: 2.55,40.45 16.2,40.45 19,37.65
  text "板厚1.2mm  2OZ   2层板" at 14.75,58.2 h2
Mechanical 3:
  lines w0.1: 2.709,19.163 3.709,19.163
Drill Drawing:
  text ".legend" at 3.95,58.25 h1.52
